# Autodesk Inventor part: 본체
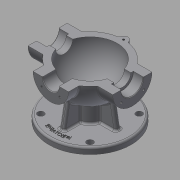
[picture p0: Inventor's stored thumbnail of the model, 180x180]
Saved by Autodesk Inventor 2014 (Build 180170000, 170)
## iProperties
Created: 2015-12
Part Number: 본체
Material: 일반
Document SubType Name: Modeling
Designer: mduedu
Density: 1 g/cm^3
Appearance: 기본값
Author: mduedu
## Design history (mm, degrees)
sketch "스케치1"
  geometry: L1 (-53, 0)-(53, 0); A1 r 53 centre (0, 0) between (53, 0) and (-53, 0); 2 further points
  constraints: 2 coincident, 2 end point, 2 point on circle, 1 centre point, 1 horizontal, 1 midpoint
  dimensions: "d0" = 53 radius of A1
revolve "회전1" sketch "스케치1" stored, may be unused: angle "d2" = 90 deg
feature "쉘1" dims "d11" = 10
node "작업 평면1"
sketch "스케치2"
  geometry: C1 r 31 at (0, 0); 1 further point
  constraints: 1 centre point, 1 coincident
  dimensions: "d4" = 62 diameter of C1
extrude "돌출1" join sketch "스케치2" stored distance "d5" = 10; taper "d6" = 0 deg
node "작업 평면2"
sketch "스케치3"
  geometry: C1 r 28 at (0, 0); 1 further point
  constraints: 1 centre point, 1 coincident
  dimensions: "d8" = 56 diameter of C1
extrude "돌출2" join sketch "스케치3" stored distance "d9" = 10; taper "d10" = 0 deg
hole "구멍1" diameter "d14" = 35; stored, may be unused: countersink angle "d18" = 90 deg, drill point angle "d20" = 0 deg; dims "d12" = 10, "d13" = 10, "d15" = 6, "d16" = 4, "d17" = 2, "d19" = 16
hole "구멍2" diameter "d23" = 27; stored, may be unused: countersink angle "d27" = 90 deg, drill point angle "d29" = 0 deg; dims "d21" = 10, "d22" = 10, "d24" = 6, "d25" = 4, "d26" = 2, "d28" = 16
fillet "모깎기1" dims "d30" = 0.3
hole "구멍3" diameter "d33" = 26; stored, may be unused: countersink angle "d37" = 90 deg, drill point angle "d39" = 0 deg; dims "d31" = 10, "d32" = 10, "d34" = 6, "d35" = 4, "d36" = 2, "d38" = 16
chamfer "모따기1" distance "d40" = 1; stored, may be unused: second distance "d41" = 2, angle "d42" = 45 deg
sketch "스케치4"
  geometry: L1 (0, 0)-(0, -25); L2 (0, 0)-(-17.678, -17.678); A1 r 25 centre (0, 0) between (-17.678, -17.678) and (0, -25); 1 further point
  constraints: 4 end point, 2 point on circle, 1 centre point, 1 coincident, 1 vertical
  dimensions: "d43" = 50 diameter of A1; "d47" = 45 deg angle of L1 L2
hole "구멍4" sketch "스케치4" at (-17.678, -17.678) diameter "d49" = 3.242; stored, may be unused: countersink angle "d53" = 90 deg, drill point angle "d55" = 118 deg; dims "d50" = 11, "d51" = 4, "d52" = 2, "d54" = 13
sketch "스케치5"
  geometry: L1 (0, 0)-(0, -20); L2 (0, 0)-(-14.142, -14.142); A1 r 20 centre (0, 0) between (0, -20) and (-14.142, -14.142); 2 further points
  constraints: 4 end point, 2 coincident, 2 point on circle, 1 centre point, 1 vertical
  dimensions: "d59" = 40 diameter of A1; "d65" = 45 deg angle of L1 L2
hole "구멍5" sketch "스케치5" at (-14.142, -14.142) diameter "d67" = 3.242; stored, may be unused: countersink angle "d71" = 90 deg, drill point angle "d73" = 118 deg; dims "d68" = 8, "d69" = 4, "d70" = 2, "d72" = 10
node "작업 평면3"
sketch "스케치6"
  geometry: C1 r 65 at (0, 0); 1 further point
  constraints: 1 centre point, 1 coincident
  dimensions: "d78" = 130 diameter of C1
extrude "돌출3" join sketch "스케치6" distance "d80" = 10; taper "d81" = 0 deg
sketch "스케치7"
  geometry: C1 r 20 at (0, 0); 1 further point
  constraints: 1 centre point, 1 coincident
  dimensions: "d82" = 40 diameter of C1
extrude "돌출4" join sketch "스케치7" stored distance "d84" = 10; taper "d85" = 0 deg
sketch "스케치8"
  geometry: 2 further points
  constraints: 1 coincident
hole "구멍6" sketch "스케치8" at (0, 0) diameter "d86" = 20; stored, may be unused: countersink angle "d90" = 90 deg, drill point angle "d92" = 118 deg; dims "d87" = 7, "d88" = 40, "d89" = 5, "d91" = 10
fillet "모깎기2" dims "d93" = 0.3
sketch "스케치9"
  geometry: L1 (65, -75)-(-65, -75) reference; L2 (-45, -75)-(-38.245, -36.692); A1 r 53 centre (0, 0) between (42.988, 31) and (42.988, -31) reference; 1 further point
  constraints: 2 end point, 1 point on circle, 1 point on line
  dimensions: "d94" = 45 horizontal distance of L2.start point (0, 0); "d95" = 80 deg angle of L2 L1
feature "리브1" sketch "스케치9" dims "d96" = 1, "d97" = 8, "d98" = 0, "d99" = 0, "d100" = 1, "d101" = 1
sketch "스케치10"
  geometry: L1 (0, 0)-(0, -55); L2 (0, 0)-(-38.891, -38.891); A1 r 55 centre (0, 0) between (0, -55) and (-38.891, -38.891); 2 further points
  constraints: 4 end point, 2 coincident, 2 point on circle, 1 centre point, 1 vertical
  dimensions: "d105" = 110 diameter of A1; "d107" = 45 deg angle of L1 L2
hole "구멍7" sketch "스케치10" at (-38.891, -38.891) diameter "d109" = 10; stored, may be unused: countersink angle "d113" = 90 deg, drill point angle "d115" = 118 deg; dims "d110" = 7, "d111" = 40, "d112" = 5, "d114" = 10
fillet "모깎기3" dims "d120" = 3
fillet "모깎기4" dims "d121" = 3, "d122" = 3
fillet "모깎기5" dims "d123" = 3
fillet "모깎기6" dims "d124" = 3
sketch "스케치11"
  geometry: C1 r 5 at (-38.891, 38.891) reference; C2 r 5 at (38.891, 38.891) reference; C3 r 5 at (38.891, -38.891) reference; C4 r 5 at (-38.891, -38.891) reference; C5 r 20 at (0, 0) reference; C6 r 65 at (0, 0) reference; 1 further point
  constraints: 3 other
feature "엠보싱1" sketch "스케치11" dims "d125" = 0.5, "d126" = 0
sketch "스케치12"
  geometry: L1 (0, 100)-(0, -100); L2 (0, 100)-(100, 100); L3 (100, 100)-(100, -100); L4 (100, -100)-(0, -100); 2 further points
  constraints: 8 end point, 3 perpendicular, 1 coincident, 1 midpoint, 1 vertical
  dimensions: "d127" = 200 distance of L2.end L3.end; "d129" = 100 distance between parallel lines of L1 L3
extrude "돌출5" cut sketch "스케치12" stored distance "d130" = 10; taper "d131" = 0 deg
sketch "스케치13"
  geometry: C1 r 7 at (0, 53); A1 r 53 centre (0, 0) between (42.113, 32.179) and (-42.113, 32.179) reference; 1 further point
  constraints: 1 centre point, 1 point on circle
  dimensions: "d132" = 14 diameter of C1
extrude "돌출6" join sketch "스케치13" distance "d134" = 15; taper "d135" = 0 deg
hole "구멍8" diameter "d139" = 3.242; stored, may be unused: countersink angle "d143" = 90 deg, drill point angle "d145" = 118 deg; dims "d140" = 8, "d141" = 4, "d142" = 2, "d144" = 10, "d148" = 10, "d149" = 10
fillet "모깎기7" dims "d146" = 3
fillet "모깎기8" dims "d147" = 3
node "솔리드1"
mirror "대칭1"
mirror "대칭2"
pattern_circular "원형 패턴1" dims angle "d57" = 360 deg
mirror "대칭3"
pattern_circular "원형 패턴2" dims angle "d75" = 360 deg
pattern_circular "원형 패턴3" dims angle "d103" = 360 deg
pattern_circular "원형 패턴4" dims angle "d118" = 360 deg
node "투영된 루프1"
other parameters: "d3" = 67, "d7" = 62, "d77" = -85
